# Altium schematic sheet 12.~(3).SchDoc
size 398 x 287 mm
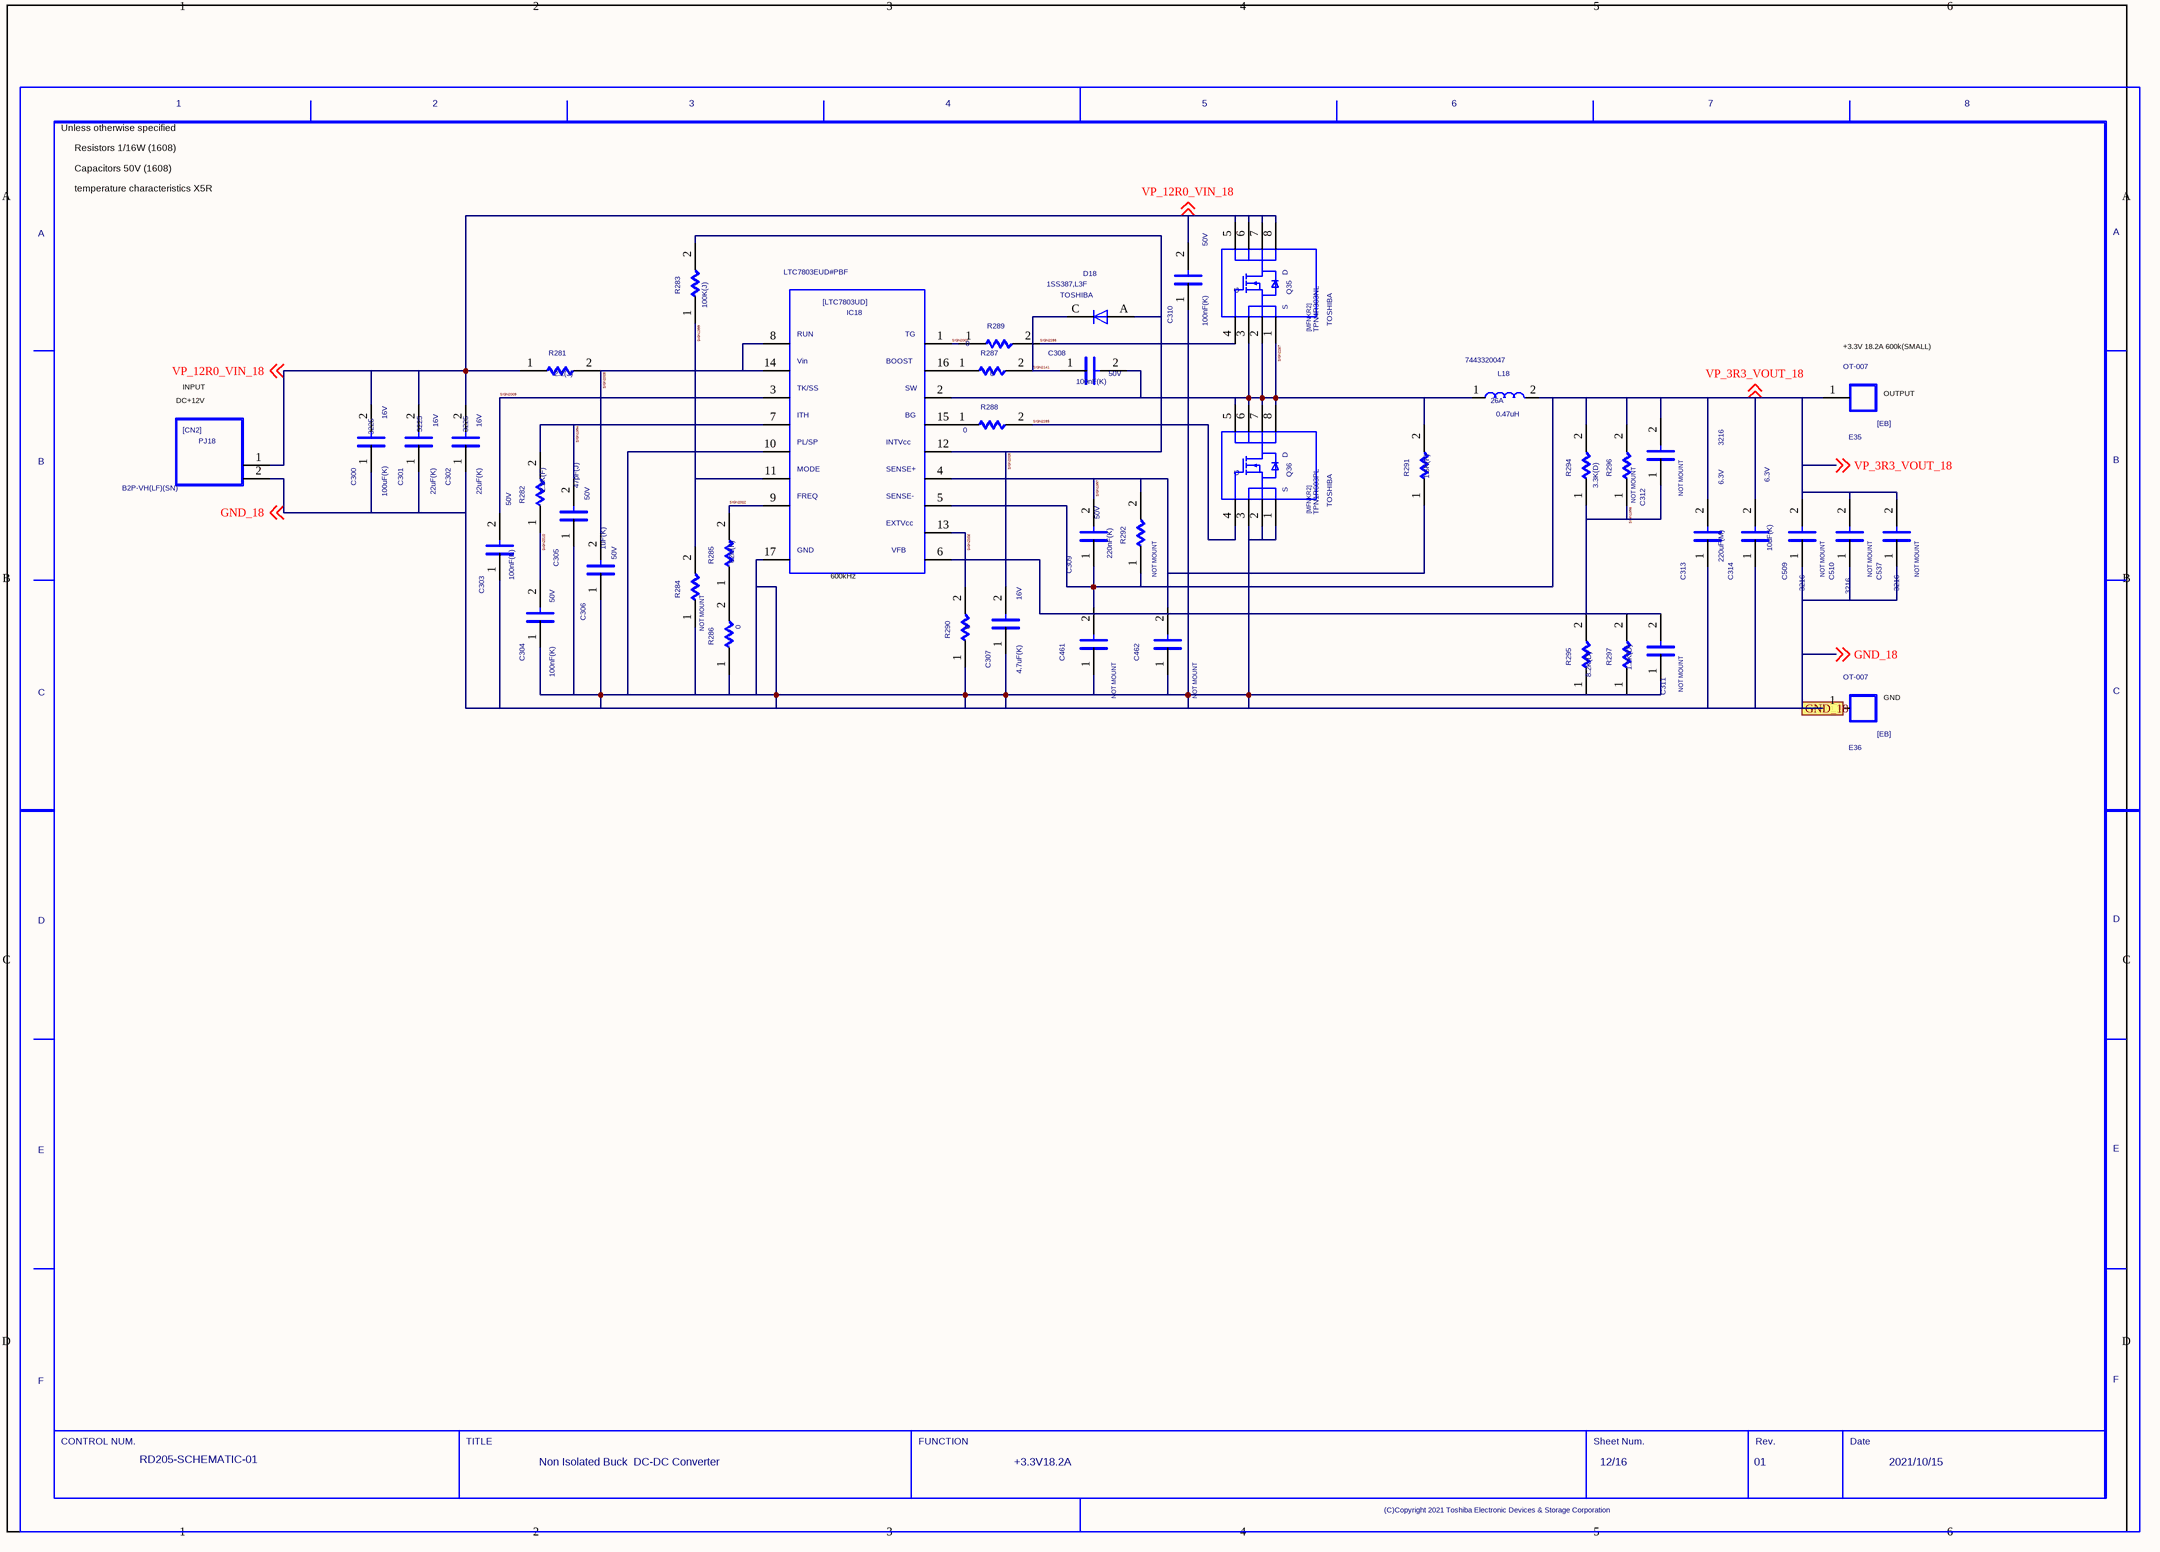
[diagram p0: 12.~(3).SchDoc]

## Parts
C300  SIZECODESMD: 3225  VAL2: 16V  VAL1: 100uF(K)  (hidden comment: C)
C301  SIZECODESMD: 3225  VAL2: 16V  VAL1: 22uF(K)  (hidden comment: C)
C302  SIZECODESMD: 3225  VAL2: 16V  VAL1: 22uF(K)  (hidden comment: C)
C303  VAL2: 50V  VAL1: 100nF(K)  (hidden comment: C)
C304  VAL2: 50V  VAL1: 100nF(K)  (hidden comment: C)
C305  VAL2: 50V  VAL1: 47pF(J)  (hidden comment: C)
C306  VAL2: 50V  VAL1: 1uF(K)  (hidden comment: C)
C307  VAL2: 16V  VAL1: 4.7uF(K)  (hidden comment: C)
C308  VAL2: 50V  VAL1: 100nF(K)  (hidden comment: C)
C309  VAL2: 50V  VAL1: 220nF(K)  (hidden comment: C)
C310  VAL2: 50V  VAL1: 100nF(K)  (hidden comment: C)
C311  NOTMOUNT: NOT MOUNT  (hidden comment: C)
C312  NOTMOUNT: NOT MOUNT  (hidden comment: C)
C313  SIZECODESMD: 3216  VAL2: 6.3V  VAL1: 220uF(M)  (hidden comment: C)
C314  VAL2: 6.3V  VAL1: 10uF(K)  (hidden comment: C)
C461  NOTMOUNT: NOT MOUNT  (hidden comment: C)
C462  NOTMOUNT: NOT MOUNT  (hidden comment: C)
C509  NOTMOUNT: NOT MOUNT  SIZECODESMD: 3216  (hidden comment: C)
C510  NOTMOUNT: NOT MOUNT  SIZECODESMD: 3216  (hidden comment: C)
C537  NOTMOUNT: NOT MOUNT  SIZECODESMD: 3216  (hidden comment: C)
D18  USERCOMPTEXT3: TOSHIBA  VAL3: 1SS387,L3F  (hidden comment: D)
E35  VAL3: OT-007  (hidden comment: EB)
E36  VAL3: OT-007  (hidden comment: EB)
IC18  VAL3: LTC7803EUD#PBF  (hidden comment: LTC7803UD)
L18  VAL3: 7443320047  VAL2: 26A  VAL1: 0.47uH  (hidden comment: L)
PJ18  VAL3: B2P-VH(LF)(SN)  (hidden comment: CN2)
Q35  USERCOMPTEXT3: TOSHIBA  VAL3: TPN4R303NL  (hidden comment: MFNKR2)
Q36  USERCOMPTEXT3: TOSHIBA  VAL3: TPN1R603PL  (hidden comment: MFNKR2)
R281  VAL1: 2.2(J)  (hidden comment: R)
R282  VAL1: 2.2K(F)  (hidden comment: R)
R283  VAL1: 100K(J)  (hidden comment: R)
R284  NOTMOUNT: NOT MOUNT  (hidden comment: R)
R285  VAL1: 62K(F)  (hidden comment: R)
R286  VAL1: 0  (hidden comment: R)
R287  VAL1: 0  (hidden comment: R)
R288  VAL1: 0  (hidden comment: R)
R289  VAL1: 0  (hidden comment: R)
R290  VAL1: 0  (hidden comment: R)
R291  VAL1: 1.5K(F)  (hidden comment: R)
R292  NOTMOUNT: NOT MOUNT  (hidden comment: R)
R294  VAL1: 3.3K(D)  (hidden comment: R)
R295  VAL1: 8.2K(D)  (hidden comment: R)
R296  NOTMOUNT: NOT MOUNT  (hidden comment: R)
R297  VAL1: 1.2K(D)  (hidden comment: R)
U?  DATE: 2021/10/15  SHEETNUMBER: 12/16  TITLE: Non Isolated Buck / DC-DC Converter  REVISION: 01  DRAWINGNUMBER: RD205-SCHEMATIC-01  FUNCTION: +3.3V18.2A  (hidden comment: WAKU_DEF100)

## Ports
GND_18

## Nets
GND_18: C300.1 C301.1 C302.1 C303.1 C304.1 C305.1 C306.1 C307.1 C310.1 C311.1 C313.1 C314.1 C461.1 C462.1 C509.1 C510.1 C537.1 E36.1 IC18.10 IC18.17 PJ18.2 Q36.1 Q36.2 Q36.3 R284.1 R286.1 R290.1 R295.1 R297.1 ; off-sheet GND_18, port GND_18
SIGN1994: C305.2 IC18.7 R282.2
SIGN1997: C309.2 C462.2 IC18.4 R291.1 R292.2
SIGN1998: C311.2 C312.1 IC18.6 R294.1 R295.2 R296.1 R297.2
SIGN1999: IC18.11 R283.1 R284.2
SIGN2002: IC18.9 R285.2
SIGN2003: IC18.1 R289.1
SIGN2005: C306.2 IC18.8 IC18.14 R281.2
SIGN2006: C307.2 D18.A IC18.12 R283.2
SIGN2008: IC18.13 R290.2
SIGN2009: C303.2 IC18.3
SIGN2010: C304.2 R282.1
SIGN2141: C308.1 D18.C R287.2
SIGN2285: Q36.4 R288.2
SIGN2286: Q35.4 R289.2
SIGN2287: C308.2 IC18.2 L18.1 Q35.1 Q35.2 Q35.3 Q36.5 Q36.6 Q36.7 Q36.8 R291.2
VP_3R3_VOUT_18: C309.1 C312.2 C313.2 C314.2 C461.2 C509.2 C510.2 C537.2 E35.1 IC18.5 L18.2 R292.1 R294.2 R296.2 ; off-sheet VP_3R3_VOUT_18
VP_12R0_VIN_18: C300.2 C301.2 C302.2 C310.2 PJ18.1 Q35.5 Q35.6 Q35.7 Q35.8 R281.1 ; off-sheet VP_12R0_VIN_18
NetIC18_15: IC18.15 R288.1
NetIC18_16: IC18.16 R287.1
NetR285_1: R285.1 R286.2

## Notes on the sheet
- Unless otherwise specified
- Resistors 1/16W (1608)
- Capacitors 50V (1608)
- temperature characteristics X5R
- DC+12V
- INPUT
- (near E35) +3.3V 18.2A 600k(SMALL)
- (near E35) OUTPUT
- (near IC18) 600kHz
- (near E36) GND

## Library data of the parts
C300 = C: SQ_PART_MODEL: CON_100n; FNPARTSNAMEG: CHIP CERAMIC CAPACITOR (3225); USEINPARTSLIST: YES; OriginalSymbolOrigin: (2540,7620); MFSOLDERINGPROP: .; TEMPCHARACTERI2: B; MFFORMINGDIVP: KC; OUMECLASSIFICATION: セラミックコンデンサ; MFMOUNTSYMBOLP: 90; CDMASTERCADCELG: DC903A; PCODE: P03276001115; FNCLASSCODEG: P03-03; MAXGCOUNT: 1; RATEDVOLTAGE: 250; COMPONENTNAME: G36030160049; OUMEMAKER: KYC 京セラ; MFPACKAGEMETHOP: S; NOMINALCAPACITA: 100n; OUMEMAKERKATAMEI: CF32W5R104K250AT; CAPACITANCETOLE: K
C301 C302 = C: SQ_PART_MODEL: CON_22u; FNPARTSNAMEG: CHIP CERAMIC CAPACITOR (3225); USEINPARTSLIST: YES; OriginalSymbolOrigin: (2540,7620); MFSOLDERINGPROP: .; TEMPCHARACTERI2: B; MFFORMINGDIVP: KC; OUMECLASSIFICATION: セラミックコンデンサ; MFMOUNTSYMBOLP: 80; CDMASTERCADCELG: DC903A; PCODE: P03043035626; FNCLASSCODEG: P03-03; MAXGCOUNT: 1; RATEDVOLTAGE: 6.3; COMPONENTNAME: G36030119054; OUMEMAKER: TYD 太陽誘電; MFPACKAGEMETHOP: S; NOMINALCAPACITA: 22u; OUMEMAKERKATAMEI: JMK325BJ226KM-T; CAPACITANCETOLE: K
C303 C304 C308 C310 = C: SQ_PART_MODEL: CON_100n; FNPARTSNAMEG: CHIP CERAMIC CAPACITOR (1608); USEINPARTSLIST: YES; OriginalSymbolOrigin: (2540,7620); MFSOLDERINGPROP: .; TEMPCHARACTERI2: B; MFFORMINGDIVP: KC; OUMECLASSIFICATION: セラミックコンデンサ; SIZECODESMD: 1608; MFMOUNTSYMBOLP: 80; CDMASTERCADCELG: C8100E; PCODE: P03B000000E4; FNCLASSCODEG: P03-03; MAXGCOUNT: 1; RATEDVOLTAGE: 16; COMPONENTNAME: GDM030000598; OUMEMAKER: MRT 村田製作所; MFPACKAGEMETHOP: S; NOMINALCAPACITA: 100n; OUMEMAKERKATAMEI: GRM188B11C104KA01C; CAPACITANCETOLE: K
C305 = C: SQ_PART_MODEL: CON_47p; FNPARTSNAMEG: CHIP CERAMIC CAPACITOR (1608); USEINPARTSLIST: YES; OriginalSymbolOrigin: (2540,7620); TOLERANCE: J; ASIMVALUE: 47P; CDMASTERCADCELG: C8100E; MFSOLDERINGPROP: .; TEMPCHARACTERI2: CH; MFFORMINGDIVP: KC; OUMECLASSIFICATION: セラミックコンデンサ; SIZECODESMD: 1608; MFMOUNTSYMBOLP: 80; PCODE: P03039A05626; FNCLASSCODEG: P03-03; MAXGCOUNT: 1; RATEDVOLTAGE: 50; COMPONENTNAME: G36030011150; OUMEMAKER: TYD 太陽誘電; MFPACKAGEMETHOP: S; OUMEMAKERKATAMEI: UMK107CH470JZ-T
C306 = C: SQ_PART_MODEL: CON_1u; FNPARTSNAMEG: CHIP CERAMIC CAPACITOR (1608); USEINPARTSLIST: YES; OriginalSymbolOrigin: (2540,7620); MFSOLDERINGPROP: .; TEMPCHARACTERI2: B; MFFORMINGDIVP: KC; OUMECLASSIFICATION: セラミックコンデンサ; SIZECODESMD: 1608; MFMOUNTSYMBOLP: 80; CDMASTERCADCELG: C8100E; PCODE: P03039ACE122; FNCLASSCODEG: P03-03; MAXGCOUNT: 1; RATEDVOLTAGE: 6.3; COMPONENTNAME: G36030104159; OUMEMAKER: KYC 京セラ; MFPACKAGEMETHOP: S; NOMINALCAPACITA: 1u; OUMEMAKERKATAMEI: CM105B105K06ATN; CAPACITANCETOLE: K
C307 = C: SQ_PART_MODEL: CON_4.7u; FNPARTSNAMEG: CHIP CERAMIC CAPACITOR (1608); USEINPARTSLIST: YES; OriginalSymbolOrigin: (2540,7620); MFSOLDERINGPROP: .; TEMPCHARACTERI2: B; MFFORMINGDIVP: KC; OUMECLASSIFICATION: セラミックコンデンサ; SIZECODESMD: 1608; MFMOUNTSYMBOLP: 80; CDMASTERCADCELG: C8100E; PCODE: P03B000000MS; FNCLASSCODEG: P03-03; MAXGCOUNT: 1; RATEDVOLTAGE: 4; COMPONENTNAME: GDM030000053; OUMEMAKER: KYC 京セラ; MFPACKAGEMETHOP: S; NOMINALCAPACITA: 4.7u; OUMEMAKERKATAMEI: CM105B475M04AT; CAPACITANCETOLE: M
C309 = C: SQ_PART_MODEL: CON_220n; FNPARTSNAMEG: CHIP CERAMIC CAPACITOR (1608); PARTCOMMENT: 代表セル<KC0008> がフットプリントに登録されていません。; USEINPARTSLIST: YES; OriginalSymbolOrigin: (2540,7620); MFSOLDERINGPROP: .; TEMPCHARACTERI2: B; MFFORMINGDIVP: KC; OUMECLASSIFICATION: セラミックコンデンサ; SIZECODESMD: 1608; MFMOUNTSYMBOLP: 80; CDMASTERCADCELG: KC0008; PCODE: P03B000001L3; FNCLASSCODEG: P03-03; MAXGCOUNT: 1; RATEDVOLTAGE: 16; COMPONENTNAME: GDM030001129; OUMEMAKER: MRT 村田製作所; MFPACKAGEMETHOP: S; NOMINALCAPACITA: 220n; OUMEMAKERKATAMEI: GRM188B11C224KA01D; CAPACITANCETOLE: K
C311 C312 = C: SQ_PART_MODEL: CON_100p; FNPARTSNAMEG: CHIP CERAMIC CAPACITOR (1608); USEINPARTSLIST: YES; OriginalSymbolOrigin: (2540,7620); TOLERANCE: J; ASIMVALUE: 100P; MFSOLDERINGPROP: .; TEMPCHARACTERI2: CH; MFFORMINGDIVP: KC; OUMECLASSIFICATION: セラミックコンデンサ; SIZECODESMD: 1608; MFMOUNTSYMBOLP: 80; CDMASTERCADCELG: C8100E; PCODE: P03039177125; FNCLASSCODEG: P03-03; MAXGCOUNT: 1; RATEDVOLTAGE: 50; COMPONENTNAME: G36030011365; OUMEMAKER: KYC 京セラ; MFPACKAGEMETHOP: S; OUMEMAKERKATAMEI: CM105CH101J50AT; VAL2: 50V; VAL1: 100pF(J)
C313 = C: SQ_PART_MODEL: CON_22u; FNPARTSNAMEG: CHIP CERAMIC CAPACITOR (3216); USEINPARTSLIST: YES; OriginalSymbolOrigin: (2540,7620); MFSOLDERINGPROP: .; TEMPCHARACTERI2: B; MFFORMINGDIVP: KC; OUMECLASSIFICATION: セラミックコンデンサ; MFMOUNTSYMBOLP: 80; CDMASTERCADCELG: DC901A; PCODE: P03B0000004V; FNCLASSCODEG: P03-03; MAXGCOUNT: 1; RATEDVOLTAGE: 6.3; COMPONENTNAME: GDM030000020; OUMEMAKER: KYC 京セラ; MFPACKAGEMETHOP: S; NOMINALCAPACITA: 22u; OUMEMAKERKATAMEI: CM316B226M06AT; CAPACITANCETOLE: M
C314 = C: SQ_PART_MODEL: CON_1u; FNPARTSNAMEG: CHIP CERAMIC CAPACITOR (1608); PARTCOMMENT: 代表セル<KC0008> がフットプリントに登録されていません。; USEINPARTSLIST: YES; OriginalSymbolOrigin: (2540,7620); MFSOLDERINGPROP: .; TEMPCHARACTERI2: B; MFPACKAGEMETHOP: S; MFFORMINGDIVP: KC; MFMOUNTSYMBOLP: 80; PCODE: P03B000000ZQ; OUMECLASSIFICATION: セラミックコンデンサ; SIZECODESMD: 1608; CDMASTERCADCELG: KC0008; FNCLASSCODEG: P03-03; MAXGCOUNT: 1; RATEDVOLTAGE: 6.3; COMPONENTNAME: GDM030000202; OUMEMAKER: MRT 村田製作所; NOMINALCAPACITA: 1u; OUMEMAKERKATAMEI: GRM185B10J105KE21D; CAPACITANCETOLE: K
C461 C462 = C: SQ_PART_MODEL: CON_220n; FNPARTSNAMEG: CHIP CERAMIC CAPACITOR (1608); PARTCOMMENT: 代表セル<KC0008> がフットプリントに登録されていません。; USEINPARTSLIST: YES; OriginalSymbolOrigin: (2540,7620); MFSOLDERINGPROP: .; TEMPCHARACTERI2: B; MFFORMINGDIVP: KC; OUMECLASSIFICATION: セラミックコンデンサ; SIZECODESMD: 1608; MFMOUNTSYMBOLP: 80; CDMASTERCADCELG: KC0008; PCODE: P03B000001L3; FNCLASSCODEG: P03-03; MAXGCOUNT: 1; RATEDVOLTAGE: 16; COMPONENTNAME: GDM030001129; OUMEMAKER: MRT 村田製作所; MFPACKAGEMETHOP: S; NOMINALCAPACITA: 220n; OUMEMAKERKATAMEI: GRM188B11C224KA01D; VAL2: 16V; VAL1: 220nF(K); CAPACITANCETOLE: K
C509 C510 C537 = C: SQ_PART_MODEL: CON_22u; FNPARTSNAMEG: CHIP CERAMIC CAPACITOR (3216); USEINPARTSLIST: YES; OriginalSymbolOrigin: (2540,7620); MFSOLDERINGPROP: .; TEMPCHARACTERI2: B; MFFORMINGDIVP: KC; OUMECLASSIFICATION: セラミックコンデンサ; MFMOUNTSYMBOLP: 80; CDMASTERCADCELG: DC901A; PCODE: P03B0000004V; FNCLASSCODEG: P03-03; MAXGCOUNT: 1; RATEDVOLTAGE: 6.3; COMPONENTNAME: GDM030000020; OUMEMAKER: KYC 京セラ; MFPACKAGEMETHOP: S; NOMINALCAPACITA: 22u; OUMEMAKERKATAMEI: CM316B226M06AT; VAL2: 6.3V; VAL1: 22uF(M); CAPACITANCETOLE: M
D18 = D: FNPARTSNAMEG: DIODE; USEINPARTSLIST: YES; PARTNAME: GDM420000143; SAVEAREA0: -565,-171,12979,8058; SAVECOUNT: 1; TIME: 14:49:55; UPDATEUSER: 19870035; UPDATETIME: 14:20:16; OriginalSymbolOrigin: (5080,5080); FORWARDVOLTAGEM: 0; MAXREVERSEVOLTA: 80; COMPONENTNAME: GDM420000143_package; MFSOLDERINGPROP: .; OUMEMAKER: TSB 東芝（ＹＰＳＳ）; QUADMODEL: dummymodel; MFPACKAGEMETHOP: S; MFFORMINGDIVP: MM; MOUNTINGFORMSMD: SMD; OUMECLASSIFICATION: 小信号ダイオード; OUMEMAKERKATAMEI: 1SS387(TPH3,F); CDMASTERCADCELG: D8101D; PCODE: P42B0000008E; FNCLASSCODEG: P42-01
E35 E36 = EB: FNPARTSNAMEG: TERMINAL; USEINPARTSLIST: YES; PARTNAME: 5P9L1232P001; OUMEPARTTYPE: TB; OriginalSymbolOrigin: (2540,12700); COMPONENTNAME: 5P9L1232P001_package; MAXGCOUNT: 1; MFSOLDERINGPROP: .; OUMEMAKER: オサダ; QUADMODEL: dummymodel; MFPACKAGEMETHOP: I; MFFORMINGDIVP: OD; OUMECLASSIFICATION: 端子台、端子板; CDMASTERCADCELG: DE0009; KIND: PBS; PCODE: P29045001117; TERMINALSTYLE: SC; FNCLASSCODEG: P29-01
IC18 = LTC7803UD: USEINPARTSLIST: YES; SAVECOUNT: 29; SAVEAREA0: -53177,0,89020,58420; TIME: 16:14:14; UPDATEUSER: q91866sr; UPDATETIME: 13:15:36; OriginalSymbolOrigin: (5080,55880); MAXGCOUNT: 1; COMPONENTNAME: LTC7803UD_LTC7803UD; OUMEMAKER: ANALOG DEVICES
L18 = L: USEINPARTSLIST: YES; PARTNAME: 7443310047; OriginalSymbolOrigin: (2540,5080); MAXGCOUNT: 1; COMPONENTNAME: L_L; OUMEMAKER: WURTH
PJ18 = CN2: FNPARTSNAMEG: 3.96PITCH NYLON CONNECTOR; USEINPARTSLIST: YES; PARTNAME: G36220114012; OUMEPARTTYPE: CN; OriginalSymbolOrigin: (2540,15240); MAXGCOUNT: 1; RATEDCURRENT: 7; COMPONENTNAME: G36220114012_package; MFSOLDERINGPROP: .; OUMEMAKER: JST 日本圧着端子製造; NUMBEROFCONTACT: 2; QUADMODEL: dummymodel; MFPACKAGEMETHOP: I; MFFORMINGDIVP: CU; CONTACTPITCH: 3.96m; OUMEMAKERKATAMEI: B2P-VH; CDMASTERCADCELG: DPJ514; PCODE: P22346001114; TERMINALSTYLE: PW; FNCLASSCODEG: P22-10
Q35 = MFNKR2: USEINPARTSLIST: YES; PARTNAME: TPN1R603PL; SAVEAREA0: -9199,-39,32138,22820; TIME: 18:57:44; UPDATEUSER: q91866sr; UPDATETIME: 12:36:02; SAVECOUNT: 10; OriginalSymbolOrigin: (5080,20320); MAXGCOUNT: 1; COMPONENTNAME: MFNKR2_MFNKR2
Q36 = MFNKR2: USEINPARTSLIST: YES; SAVEAREA0: -9199,-39,32138,22820; TIME: 18:57:44; UPDATEUSER: q91866sr; UPDATETIME: 12:36:02; SAVECOUNT: 10; OriginalSymbolOrigin: (5080,20320); MAXGCOUNT: 1; COMPONENTNAME: MFNKR2_MFNKR2
R281 = R: SQ_PART_MODEL: RES_2.2; FNPARTSNAMEG: CHIP RESISTOR (1608); USEINPARTSLIST: YES; OriginalSymbolOrigin: (5080,5080); TOLERANCE: J; ASIMVALUE: 2.2; MAXGCOUNT: 1; COMPONENTNAME: G36010011507; MFSOLDERINGPROP: .; OUMEMAKER: NAE 松下電子部品; MFPACKAGEMETHOP: S; MFFORMINGDIVP: KC; MOUNTINGFORMSMD: SMD; OUMECLASSIFICATION: 表面実装用固定抵抗器; MFMOUNTSYMBOLP: 80; POWERRATING: 63m; OUMEMAKERKATAMEI: ERJ3GEYJ2R2V; NUMBEROFELEMENT: 0; VAL2: 62.5mW; CDMASTERCADCELG: DR802R; PCODE: P01042157622; FNCLASSCODEG: P01-08
R282 = R: SQ_PART_MODEL: RES_2.2K; FNPARTSNAMEG: CHIP RESISTOR (1608); USEINPARTSLIST: YES; OriginalSymbolOrigin: (5080,5080); MAXGCOUNT: 1; COMPONENTNAME: G36010104339; MFSOLDERINGPROP: .; OUMEMAKER: KOA ＫＯＡ; MFPACKAGEMETHOP: S; MFFORMINGDIVP: KC; MOUNTINGFORMSMD: SMD; OUMECLASSIFICATION: 表面実装用固定抵抗器; RESISTANCETOLER: F; MFMOUNTSYMBOLP: 80; POWERRATING: 63m; OUMEMAKERKATAMEI: RK73H1JTD2201F; NOMINALRESISTAN: 2.2K; NUMBEROFELEMENT: 0; VAL2: 62.5mW; CDMASTERCADCELG: DR802R; PCODE: P01042159428; FNCLASSCODEG: P01-08
R283 = R: SQ_PART_MODEL: RES_100K; FNPARTSNAMEG: CHIP RESISTOR (1608); USEINPARTSLIST: YES; OriginalSymbolOrigin: (5080,5080); TOLERANCE: F; ASIMVALUE: 100K; MFSOLDERINGPROP: .; MFPACKAGEMETHOP: S; MFFORMINGDIVP: KC; MOUNTINGFORMSMD: SMD; MFMOUNTSYMBOLP: 80; NUMBEROFELEMENT: 0; PCODE: P01042045226; MAXGCOUNT: 1; COMPONENTNAME: G36010011057; OUMEMAKER: HDK 北陸電気工業; OUMECLASSIFICATION: 表面実装用固定抵抗器; POWERRATING: 63m; OUMEMAKERKATAMEI: CR1/16 104FV; VAL2: 62.5mW; CDMASTERCADCELG: DR802R; FNCLASSCODEG: P01-08
R284 = R: SQ_PART_MODEL: RES_10; FNPARTSNAMEG: CHIP RESISTOR (1608); USEINPARTSLIST: YES; OriginalSymbolOrigin: (5080,5080); TOLERANCE: F; ASIMVALUE: 10; MFSOLDERINGPROP: .; MFPACKAGEMETHOP: S; MFFORMINGDIVP: KC; MOUNTINGFORMSMD: SMD; MFMOUNTSYMBOLP: 80; NUMBEROFELEMENT: 0; PCODE: P01042036620; MAXGCOUNT: 1; COMPONENTNAME: G36010104063; OUMEMAKER: NAE 松下電子部品; OUMECLASSIFICATION: 表面実装用固定抵抗器; POWERRATING: 63m; OUMEMAKERKATAMEI: ERJ3GEYF100V; VAL2: 62.5mW; VAL1: 10(F); CDMASTERCADCELG: DR802R; FNCLASSCODEG: P01-08
R285 = R: SQ_PART_MODEL: RES_62K; FNPARTSNAMEG: CHIP RESISTOR (1608); USEINPARTSLIST: YES; OriginalSymbolOrigin: (5080,5080); MAXGCOUNT: 1; COMPONENTNAME: GDM010001037; MFSOLDERINGPROP: .; OUMEMAKER: NAE 松下電子部品; MFPACKAGEMETHOP: S; MFFORMINGDIVP: KC; MOUNTINGFORMSMD: SMD; OUMECLASSIFICATION: 表面実装用固定抵抗器; RESISTANCETOLER: F; MFMOUNTSYMBOLP: 80; POWERRATING: 63m; OUMEMAKERKATAMEI: ERJ3GEYF623V; NOMINALRESISTAN: 62K; NUMBEROFELEMENT: 0; VAL2: 62.5mW; CDMASTERCADCELG: DR802R; PCODE: P01042441622; FNCLASSCODEG: P01-08
R286 = R: SQ_PART_MODEL: RES_160K; FNPARTSNAMEG: CHIP RESISTOR (1608); USEINPARTSLIST: YES; OriginalSymbolOrigin: (5080,5080); MAXGCOUNT: 1; COMPONENTNAME: G51011061108; MFSOLDERINGPROP: .; OUMEMAKER: HDK 北陸電気工業; MFPACKAGEMETHOP: S; MFFORMINGDIVP: KC; MOUNTINGFORMSMD: SMD; OUMECLASSIFICATION: 表面実装用固定抵抗器; RESISTANCETOLER: F; MFMOUNTSYMBOLP: 80; POWERRATING: 63m; OUMEMAKERKATAMEI: CR1/16 164FV; NOMINALRESISTAN: 160K; VAL2: 62.5mW; CDMASTERCADCELG: DR802R; PCODE: P01042125225; FNCLASSCODEG: P01-08
R287 R290 = R: SQ_PART_MODEL: RES_10; FNPARTSNAMEG: CHIP RESISTOR (1608); USEINPARTSLIST: YES; OriginalSymbolOrigin: (5080,5080); TOLERANCE: F; ASIMVALUE: 10; MFSOLDERINGPROP: .; MFPACKAGEMETHOP: S; MFFORMINGDIVP: KC; MOUNTINGFORMSMD: SMD; MFMOUNTSYMBOLP: 80; PCODE: P01042036620; MAXGCOUNT: 1; COMPONENTNAME: G36010104063; OUMEMAKER: NAE 松下電子部品; OUMECLASSIFICATION: 表面実装用固定抵抗器; POWERRATING: 63m; OUMEMAKERKATAMEI: ERJ3GEYF100V; VAL2: 62.5mW; CDMASTERCADCELG: DR802R; FNCLASSCODEG: P01-08
R288 R289 = R: SQ_PART_MODEL: RES_10; FNPARTSNAMEG: CHIP RESISTOR (2012); USEINPARTSLIST: YES; OriginalSymbolOrigin: (5080,5080); MAXGCOUNT: 1; TOLERANCE: F; COMPONENTNAME: 5P9L1083P100; MFSOLDERINGPROP: .; OUMEMAKER: 北陸電気工業; MFPACKAGEMETHOP: S; MFFORMINGDIVP: KC; MOUNTINGFORMSMD: SMD; OUMECLASSIFICATION: 表面実装用固定抵抗器; ASIMVALUE: 10; MFMOUNTSYMBOLP: 90; POWERRATING: 100m; OUMEMAKERKATAMEI: CR1/10 100FV Pb(F); VAL2: 125mW; CDMASTERCADCELG: DR910A; PCODE: P01043091222; FNCLASSCODEG: P01-08
R291 = R: SQ_PART_MODEL: RES_1.5K; FNPARTSNAMEG: CHIP RESISTOR (1608); USEINPARTSLIST: YES; OriginalSymbolOrigin: (5080,5080); TOLERANCE: F; ASIMVALUE: 1.5K; MAXGCOUNT: 1; COMPONENTNAME: G36010027232; MFSOLDERINGPROP: .; OUMEMAKER: HDK 北陸電気工業; MFPACKAGEMETHOP: S; MFFORMINGDIVP: KC; MOUNTINGFORMSMD: SMD; OUMECLASSIFICATION: 表面実装用固定抵抗器; MFMOUNTSYMBOLP: 80; POWERRATING: 63m; OUMEMAKERKATAMEI: CR1/16 152FV; NUMBEROFELEMENT: 0; VAL2: 62.5mW; CDMASTERCADCELG: DR802R; PCODE: P01042512223; FNCLASSCODEG: P01-08
R292 = R: SQ_PART_MODEL: RES_68K; FNPARTSNAMEG: CHIP RESISTOR (1608); USEINPARTSLIST: YES; OriginalSymbolOrigin: (5080,5080); TOLERANCE: F; ASIMVALUE: 68K; MAXGCOUNT: 1; COMPONENTNAME: G36010027126; OUMEMAKER: HDK 北陸電気工業; MOUNTINGFORMSMD: SMD; OUMECLASSIFICATION: 表面実装用固定抵抗器; POWERRATING: 63m; OUMEMAKERKATAMEI: CR1/16 683FV; CDMASTERCADCELG: DR802R; MFSOLDERINGPROP: .; MFPACKAGEMETHOP: S; MFFORMINGDIVP: KC; MFMOUNTSYMBOLP: 80; NUMBEROFELEMENT: 0; VAL2: 62.5mW; VAL1: 68K(F); PCODE: P01042456220; FNCLASSCODEG: P01-08
R294 = R: SQ_PART_MODEL: RES_3.3K; FNPARTSNAMEG: CHIP RESISTOR (1608); USEINPARTSLIST: YES; OriginalSymbolOrigin: (5080,5080); MAXGCOUNT: 1; COMPONENTNAME: G36010014485; MFSOLDERINGPROP: .; OUMEMAKER: SSM 進工業; MFPACKAGEMETHOP: S; MFFORMINGDIVP: KC; MOUNTINGFORMSMD: SMD; OUMECLASSIFICATION: 表面実装用固定抵抗器; RESISTANCETOLER: D; MFMOUNTSYMBOLP: 80; POWERRATING: 63m; OUMEMAKERKATAMEI: RR0816P-332-D; NOMINALRESISTAN: 3.3K; NUMBEROFELEMENT: 0; VAL2: 62.5mW; CDMASTERCADCELG: DR802R; PCODE: P01042249822; FNCLASSCODEG: P01-08
R295 = R: ICX_PART_MODEL: RES_8.2K; FNPARTSNAMEG: CHIP RESISTOR (1608); OriginalSymbolOrigin: (5080,5080); FNCLASSCODEG: P01-08; PCODE: P01117051114; CDMASTERCADCELG: DR802R; USEWITHSCHEMA: YES; VAL2: 62.5mW; NUMBEROFELEMENT: 0; NOMINALRESISTAN: 8.2K; OUMEMAKERKATAMEI: RK73G1JTD822D; POWERRATING: 63m; MFMOUNTSYMBOLP: 80; RESISTANCETOLER: D; FUNCTION: G36010129479; OUMECLASSIFICATION: 表面実装用固定抵抗器; MOUNTINGFORMSMD: SMD; MFFORMINGDIVP: KC; MFPACKAGEMETHOP: S; OUMEMAKER: KOA ＫＯＡ; MFSOLDERINGPROP: .; MAXGCOUNT: 1
R296 = R: SQ_PART_MODEL: RES_3.3K; FNPARTSNAMEG: CHIP RESISTOR (1608); USEINPARTSLIST: YES; OriginalSymbolOrigin: (5080,5080); TOLERANCE: F; ASIMVALUE: 3.3K; MAXGCOUNT: 1; COMPONENTNAME: G36010027027; MFSOLDERINGPROP: .; OUMEMAKER: ROH ロー・; MFPACKAGEMETHOP: S; MFFORMINGDIVP: KC; MOUNTINGFORMSMD: SMD; OUMECLASSIFICATION: 表面実装用固定抵抗器; MFMOUNTSYMBOLP: 80; POWERRATING: 63m; OUMEMAKERKATAMEI: MCR03EZPFX3301; NUMBEROFELEMENT: 0; VAL2: 62.5mW; VAL1: 3.3K(F); CDMASTERCADCELG: DR802R; PCODE: P01042250729; FNCLASSCODEG: P01-08
R297 = R: ICX_PART_MODEL: RES_1.2K; FNPARTSNAMEG: CHIP RESISTOR (1608); OriginalSymbolOrigin: (5080,5080); FNCLASSCODEG: P01-08; PCODE: P01117031116; CDMASTERCADCELG: DR802R; USEWITHSCHEMA: YES; VAL2: 62.5mW; NUMBEROFELEMENT: 0; NOMINALRESISTAN: 1.2K; OUMEMAKERKATAMEI: RK73G1JTD122D; POWERRATING: 63m; MFMOUNTSYMBOLP: 80; RESISTANCETOLER: D; FUNCTION: G36010129271; OUMECLASSIFICATION: 表面実装用固定抵抗器; MOUNTINGFORMSMD: SMD; MFFORMINGDIVP: KC; MFPACKAGEMETHOP: S; OUMEMAKER: KOA ＫＯＡ; MFSOLDERINGPROP: .; MAXGCOUNT: 1
U? = WAKU_DEF100: PLOTTIME: HH:MM; SAVEAREA0: 330961,54,387907,31546; TIME: 19:23:07; UPDATEUSER: t5459927; UPDATETIME: 15:33:42; SAVECOUNT: 6; OriginalSymbolOrigin: (10160,284480); DESIGNED: ***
